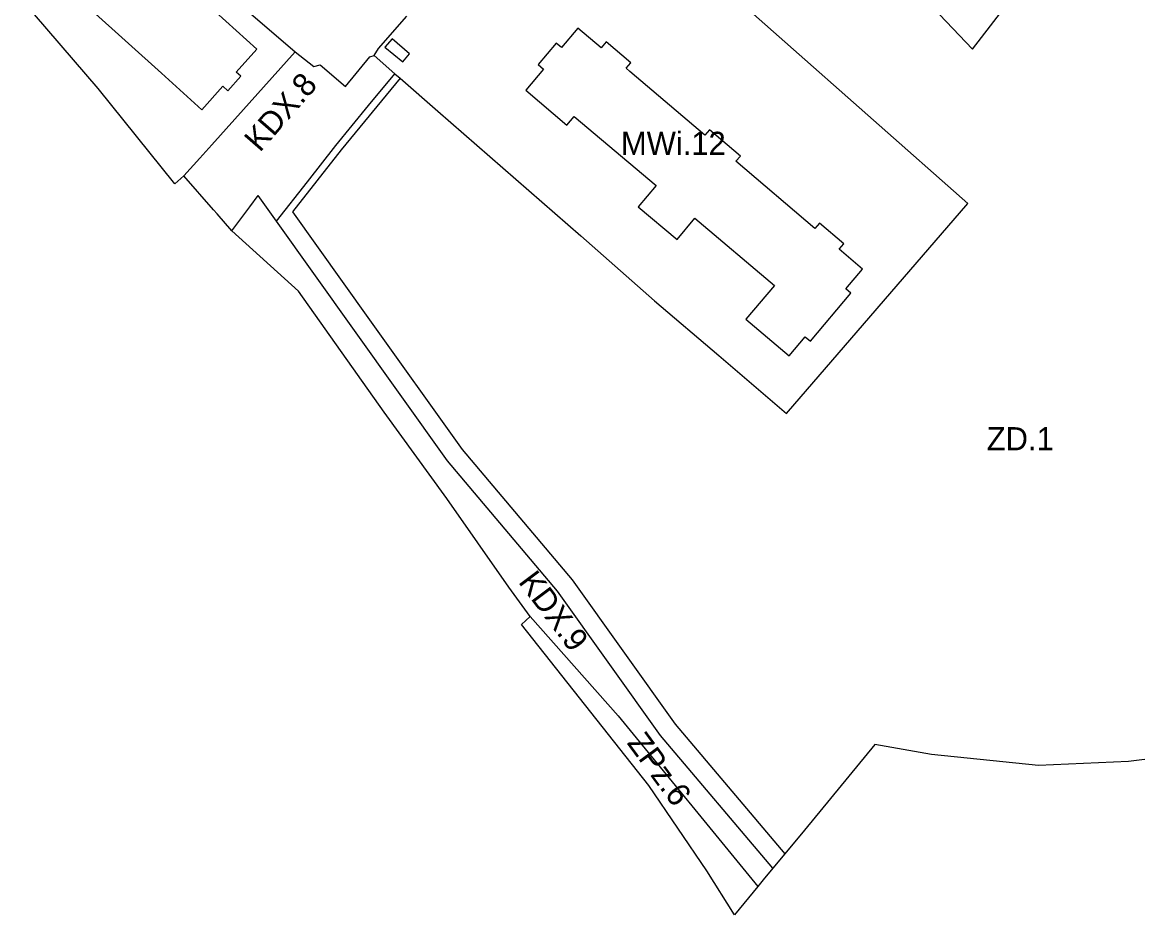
# Model space of a CAD drawing. Extents: x 7425067 to 7426806, y 5549054 to 5550619.
# Drawn here: x 7426300.5 to 7426541.6, y 5549054.3 to 5549247.2 of the extents above; entities that cross this region are included whole.
import ezdxf

# ---------------------------------------------------------------- set-up
doc = ezdxf.new("R2010")
doc.units = 0
for name, color, linetype in [('LIN_Linia Zabudowy Nieprzekraczalna', 7, 'Continuous'), ('LIN_linia zabudowy obowiązująca', 7, 'Continuous'), ('LIN_linie_rozgraniczajace', 7, 'Continuous'), ('TXT_Oznaczenia_przeznaczen', 7, 'Continuous')]:
    doc.layers.add(name, color=color, linetype=linetype)

msp = doc.modelspace()

# ---------------------------------------------------------------- linework, layer by layer
at = {"layer": 'LIN_Linia Zabudowy Nieprzekraczalna'}
for points in [[(7426308.7359, 5549260.9235), (7426307.3308, 5549259.3369), (7426315.5649, 5549249.7426), (7426330.51, 5549236.22), (7426339.23, 5549228.33)], [(7426339.23, 5549228.33), (7426343.8, 5549233.39), (7426344.85, 5549232.44), (7426347.68, 5549235.57), (7426346.68, 5549236.47), (7426351.16, 5549241.43), (7426342.23, 5549249.5)], [(7426382.1121, 5549235.1142), (7426369.3676, 5549219.6299), (7426358.8747, 5549206.2416)], [(7426358.8747, 5549206.2416), (7426375.1718, 5549183.3874)], [(7426375.1718, 5549183.3874), (7426395.5308, 5549154.837)], [(7426395.5308, 5549154.837), (7426419.342, 5549126.6855)], [(7426419.342, 5549126.6855), (7426441.5564, 5549095.4714)], [(7426441.5564, 5549095.4714), (7426465.2776, 5549067.4577)]]:
    msp.add_lwpolyline(points, dxfattribs=at)
at = {"layer": 'LIN_linia zabudowy obowiązująca'}
for points in [[(7426409.29, 5549232.52), (7426418.2, 5549225.01), (7426419.74, 5549226.85), (7426437.45, 5549211.93), (7426433.58, 5549207.34), (7426441.99, 5549200.26), (7426445.86, 5549204.85), (7426463.07, 5549190.35), (7426456.88, 5549183.01), (7426466.25, 5549175.12), (7426469.73, 5549179.25), (7426470.88, 5549178.28), (7426479.59, 5549188.63), (7426478.47, 5549189.57), (7426482.1, 5549193.88), (7426477.04, 5549198.18), (7426478.03, 5549199.36), (7426472.78, 5549203.83), (7426471.78, 5549202.65), (7426454.73, 5549217.18), (7426455.7, 5549218.32), (7426449.04, 5549224), (7426448.03, 5549222.81), (7426431.799, 5549236.5859), (7426431, 5549237.32), (7426431.98, 5549238.46), (7426426.69, 5549242.97), (7426425.62, 5549241.73), (7426420.56, 5549245.96), (7426417, 5549241.76), (7426415.89, 5549242.71), (7426411.96, 5549238.09)], [(7426378.85, 5549241.88), (7426382.7, 5549238.71), (7426384.18, 5549240.43), (7426380.4, 5549243.68), (7426378.85, 5549241.88)], [(7426411.96, 5549238.09), (7426413.14, 5549237.1), (7426409.29, 5549232.52)]]:
    msp.add_lwpolyline(points, dxfattribs=at)
at = {"layer": 'LIN_linie_rozgraniczajace'}
for points in [[(7426476.61, 5549273.5), (7426477.6833, 5549272.2774), (7426486.53, 5549262.2), (7426494.45, 5549253.45), (7426505.87, 5549241.45)], [(7426504.87, 5549208.07), (7426443.6501, 5549262.175), (7426439.39, 5549265.94)], [(7426505.87, 5549241.45), (7426520.96, 5549261.01)], [(7426316.85, 5549232.89), (7426300.45, 5549252)], [(7426349.305, 5549249.565), (7426359.45, 5549240.86)], [(7426377.42, 5549241.53), (7426383.61, 5549248.54)], [(7426359.45, 5549240.86), (7426341.45, 5549220.765)], [(7426359.45, 5549240.86), (7426363.47, 5549237.66)], [(7426376.5, 5549240.02), (7426377.42, 5549241.53)], [(7426363.47, 5549237.66), (7426364.85, 5549238)], [(7426364.85, 5549238), (7426370.31, 5549233.36)], [(7426370.31, 5549233.36), (7426375.55, 5549239.73)], [(7426375.55, 5549239.73), (7426376.5, 5549240.02)], [(7426376.5, 5549240.02), (7426380.96, 5549236.12)], [(7426375.3284, 5549229.2308), (7426380.9816, 5549236.1012)], [(7426380.96, 5549236.12), (7426380.9816, 5549236.1012), (7426382.1121, 5549235.1142), (7426390.25, 5549228.01)], [(7426333.46, 5549212.32), (7426316.85, 5549232.89)], [(7426368.1971, 5549220.5681), (7426375.3284, 5549229.2308)], [(7426390.25, 5549228.01), (7426421.19, 5549201.07)], [(7426341.45, 5549220.765), (7426338.8462, 5549217.8582)], [(7426362.0859, 5549212.7704), (7426368.1971, 5549220.5681)], [(7426338.8462, 5549217.8582), (7426335.38, 5549214)], [(7426335.38, 5549214), (7426333.46, 5549212.32)], [(7426341.79, 5549206.69), (7426335.38, 5549214)], [(7426355.3942, 5549204.2329), (7426362.0859, 5549212.7704)], [(7426349.6351, 5549207.3275), (7426351.46, 5549209.75)], [(7426371.915, 5549181.065), (7426355.3942, 5549204.2329), (7426351.46, 5549209.75)], [(7426342.58, 5549205.79), (7426341.79, 5549206.69)], [(7426345.75, 5549202.17), (7426349.6351, 5549207.3275)], [(7426465.68, 5549162.66), (7426504.87, 5549208.07)], [(7426345.75, 5549202.17), (7426342.58, 5549205.79)], [(7426360.16, 5549189.12), (7426345.75, 5549202.17)], [(7426421.19, 5549201.07), (7426437.13, 5549187.01)], [(7426378.67, 5549162.93), (7426360.16, 5549189.12)], [(7426437.13, 5549187.01), (7426451.01, 5549175.22)], [(7426392.37, 5549152.38), (7426371.915, 5549181.065)], [(7426451.01, 5549175.22), (7426465.68, 5549162.66)], [(7426392.23, 5549144.25), (7426378.67, 5549162.93)], [(7426416.18, 5549124.23), (7426392.37, 5549152.38)], [(7426405.65, 5549125.12), (7426392.23, 5549144.25)], [(7426410.26, 5549118.75), (7426405.65, 5549125.12)], [(7426438.395, 5549093.015), (7426416.18, 5549124.23)], [(7426408.4, 5549117.03), (7426410.26, 5549118.75)], [(7426410.26, 5549118.75), (7426429.2542, 5549097.2662)], [(7426435.92, 5549082.21), (7426408.4, 5549117.03)], [(7426429.2542, 5549097.2662), (7426459.4483, 5549060.3905)], [(7426462.691, 5549064.3225), (7426438.395, 5549093.015)], [(7426484.77, 5549091.08), (7426469.52, 5549072.6)], [(7426496.98, 5549088.91), (7426484.77, 5549091.08)], [(7426520.12, 5549086.53), (7426496.98, 5549088.91)], [(7426559.4, 5549089.83), (7426539.6, 5549087.43)], [(7426539.6, 5549087.43), (7426520.12, 5549086.53)], [(7426448.45, 5549063.77), (7426435.92, 5549082.21)], [(7426469.52, 5549072.6), (7426465.2776, 5549067.4577), (7426462.691, 5549064.3225), (7426460.61, 5549061.8)], [(7426454.42, 5549054.29), (7426448.45, 5549063.77)], [(7426460.61, 5549061.8), (7426459.4483, 5549060.3905), (7426454.42, 5549054.29)]]:
    msp.add_lwpolyline(points, dxfattribs=at)

# ---------------------------------------------------------------- texts
at = {"layer": 'TXT_Oznaczenia_przeznaczen'}
for s, rotation, p in [('KDX.8', 48.969139, (7426351.7996, 5549218.9601)), ('KDX.9', 306.904534, (7426407.5419, 5549126.2158)), ('ZPz.6', 306.2945, (7426431.032, 5549091.396))]:
    msp.add_text(s, height=5, rotation=rotation, dxfattribs=at).set_placement(p)
for s, p in [('MWi.12', (7426429.8644, 5549218.5595)), ('ZD.1', (7426508.9479, 5549154.6956))]:
    msp.add_text(s, height=5, dxfattribs=at).set_placement(p)

doc.saveas('drawing.dxf')
